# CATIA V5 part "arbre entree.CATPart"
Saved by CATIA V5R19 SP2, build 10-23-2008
Part number: arbre entree
Publications: "diametre arbre entree"
Bounding box of the stored display mesh (mm): x -60 to 0, y -4 to 4, z -3.991 to 3.991
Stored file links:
  C:\Users\Thinkmotion2\Desktop\Pack 1\IAO_2010_1396_fvigouroux\vigouroux\vigouroux\arbre entree.CATPart
  C:\Users\Thinkmotion2\Desktop\Pack 1\IAO_2010_1396_fvigouroux\vigouroux\vigouroux\mecanisme IAO.CATProduct
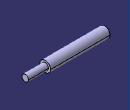
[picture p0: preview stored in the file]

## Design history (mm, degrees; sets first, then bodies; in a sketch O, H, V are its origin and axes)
Parameters
  `diametre arbre entree` = 4 mm
External parameters (linked from other documents)
  `External.diametre bati` = 2.5 mm
Set1
  Plane1: linked copy from another document
  Point1: linked copy from another document
  Plane2: linked copy from another document
  Point2: linked copy from another document
  Plane3: linked copy from another document
  Plane4: linked copy from another document
Body1 (main body)
  Sketch1 on Plane1, origin (0, 0, 0), H (0, 1, 0), V (0, 0, 1)
    circle A1 centre (0, 0) radius 2.5
    point P1 (0, 0)
    reference projected point E1 (0, 0) from Point1
    distance P1 E1 = 0
    radius A1 = 2.5 {= `External.diametre bati`}
    coincidence: P1 H
  Pad1: profile Sketch1, direction (-1, 0, 0), up to Plane2
  Sketch2 on Plane2, origin (-15, 0, 0), H (0, 1, 0), V (0, 0, 1)
    circle A1 centre (0, 0) radius 4
    point P1 (0, 0)
    reference projected point E1 (0, 0) from Point2
    radius A1 = 4 {= `diametre arbre entree`}
    distance E1 P1 = 0
    coincidence: P1 H
  Pad2: profile Sketch2, direction (1, 0, 0), up to Plane4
